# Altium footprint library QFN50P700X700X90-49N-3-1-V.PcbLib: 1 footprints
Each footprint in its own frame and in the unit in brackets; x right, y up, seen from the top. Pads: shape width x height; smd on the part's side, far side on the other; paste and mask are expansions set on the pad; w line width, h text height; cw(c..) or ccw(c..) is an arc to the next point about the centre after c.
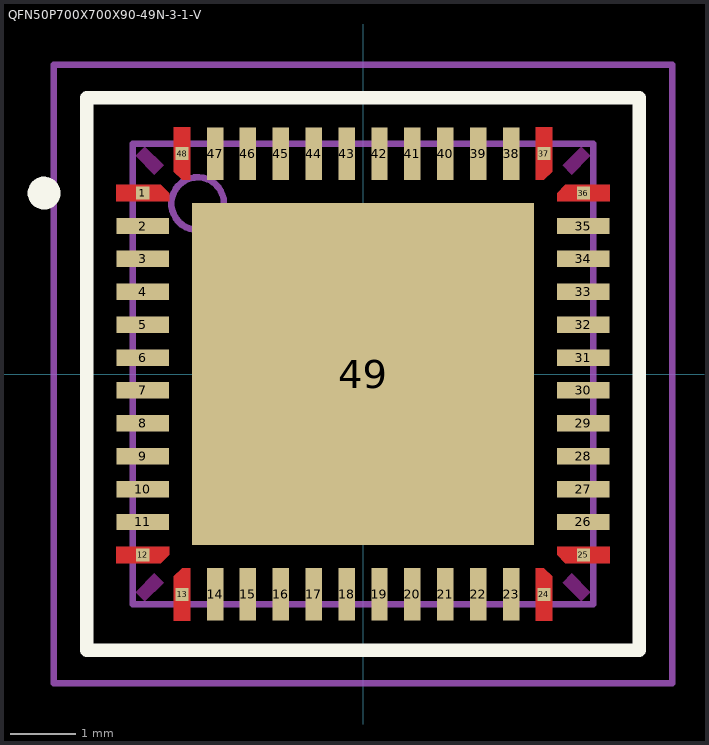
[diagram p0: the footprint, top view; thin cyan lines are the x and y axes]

## QFN50P700X700X90-49N-3-1-V [mm] "QFN,0.50mm pitch,square;48 pin,7.00mm L X 7.00mm W X 0.90mm H body (w/thermal tab)"
height 0.9
pads (49):
  rect 0.2x0.2 smd paste-0.1 mask-0.1: 1(-3.35,2.75) 12(-3.35,-2.75) 13(-2.75,-3.35) 24(2.75,-3.35) 25(3.35,-2.75) 36(3.35,2.75) 37(2.75,3.35) 48(-2.75,3.35)
  rect 0.8x0.25 smd paste+0 mask+0: 2(-3.35,2.25) 3(-3.35,1.75) 4(-3.35,1.25) 5(-3.35,0.75) 6(-3.35,0.25) 7(-3.35,-0.25) 8(-3.35,-0.75) 9(-3.35,-1.25) 10(-3.35,-1.75) 11(-3.35,-2.25) 26(3.35,-2.25) 27(3.35,-1.75) 28(3.35,-1.25) 29(3.35,-0.75) 30(3.35,-0.25) 31(3.35,0.25) 32(3.35,0.75) 33(3.35,1.25) 34(3.35,1.75) 35(3.35,2.25)
  rect 0.25x0.8 smd paste+0 mask+0: 14(-2.25,-3.35) 15(-1.75,-3.35) 16(-1.25,-3.35) 17(-0.75,-3.35) 18(-0.25,-3.35) 19(0.25,-3.35) 20(0.75,-3.35) 21(1.25,-3.35) 22(1.75,-3.35) 23(2.25,-3.35) 38(2.25,3.35) 39(1.75,3.35) 40(1.25,3.35) 41(0.75,3.35) 42(0.25,3.35) 43(-0.25,3.35) 44(-0.75,3.35) 45(-1.25,3.35) 46(-1.75,3.35) 47(-2.25,3.35)
  rect 5.2x5.2 smd paste+0 mask+0: 49(0,0)
Top Layer:
  region: 3.75,-2.875 3.75,-2.625 2.95,-2.625 2.95,-2.75 3.075,-2.875
  region: -2.875,3.75 -2.625,3.75 -2.625,2.95 -2.75,2.95 -2.875,3.075
  region: -3.75,-2.875 -3.75,-2.625 -2.95,-2.625 -2.95,-2.75 -3.075,-2.875
  region: 3.75,2.875 3.75,2.625 2.95,2.625 2.95,2.75 3.075,2.875
  region: 2.875,-3.75 2.625,-3.75 2.625,-2.95 2.75,-2.95 2.875,-3.075
  region: 2.875,3.75 2.625,3.75 2.625,2.95 2.75,2.95 2.875,3.075
  region: -2.875,-3.75 -2.625,-3.75 -2.625,-2.95 -2.75,-2.95 -2.875,-3.075
  region: -3.75,2.875 -3.75,2.625 -2.95,2.625 -2.95,2.75 -3.075,2.875
Top Layer keep-out:
  region: 3.316,3.457 3.457,3.316 3.174,3.033 3.033,3.174
  region: 3.457,-3.316 3.316,-3.457 3.033,-3.174 3.174,-3.033
  region: -3.316,-3.457 -3.457,-3.316 -3.174,-3.033 -3.033,-3.174
  region: -3.457,3.316 -3.316,3.457 -3.033,3.174 -3.174,3.033
Top Overlay:
  circle w0.25: c-4.85,2.75 r0.125
  lines w0.2: -4.2,-4.2 -4.2,4.2 4.2,4.2 4.2,-4.2 -4.2,-4.2
M3 (ASY_Text_Top):
  text ".DESIGNATOR" at 0,0 h1.2
M13 (CMP_Body_OTL_Top):
  circle w0.1: c-2.515,2.591 r0.4
  lines w0.1: -3.5,-3.5 3.5,-3.5 3.5,3.5 -3.5,3.5 -3.5,-3.5
M15 (CMP_Courtyard_Top):
  lines w0.1: -0.5,0 0.5,0 ; 0,-0.5 0,0.5 ; -4.7,-4.7 -4.7,4.7 4.7,4.7 4.7,-4.7 -4.7,-4.7
3D body "VQFN-48.stp": height 0.91, standoff 0, extent -3.5,-3.5 3.5,3.5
